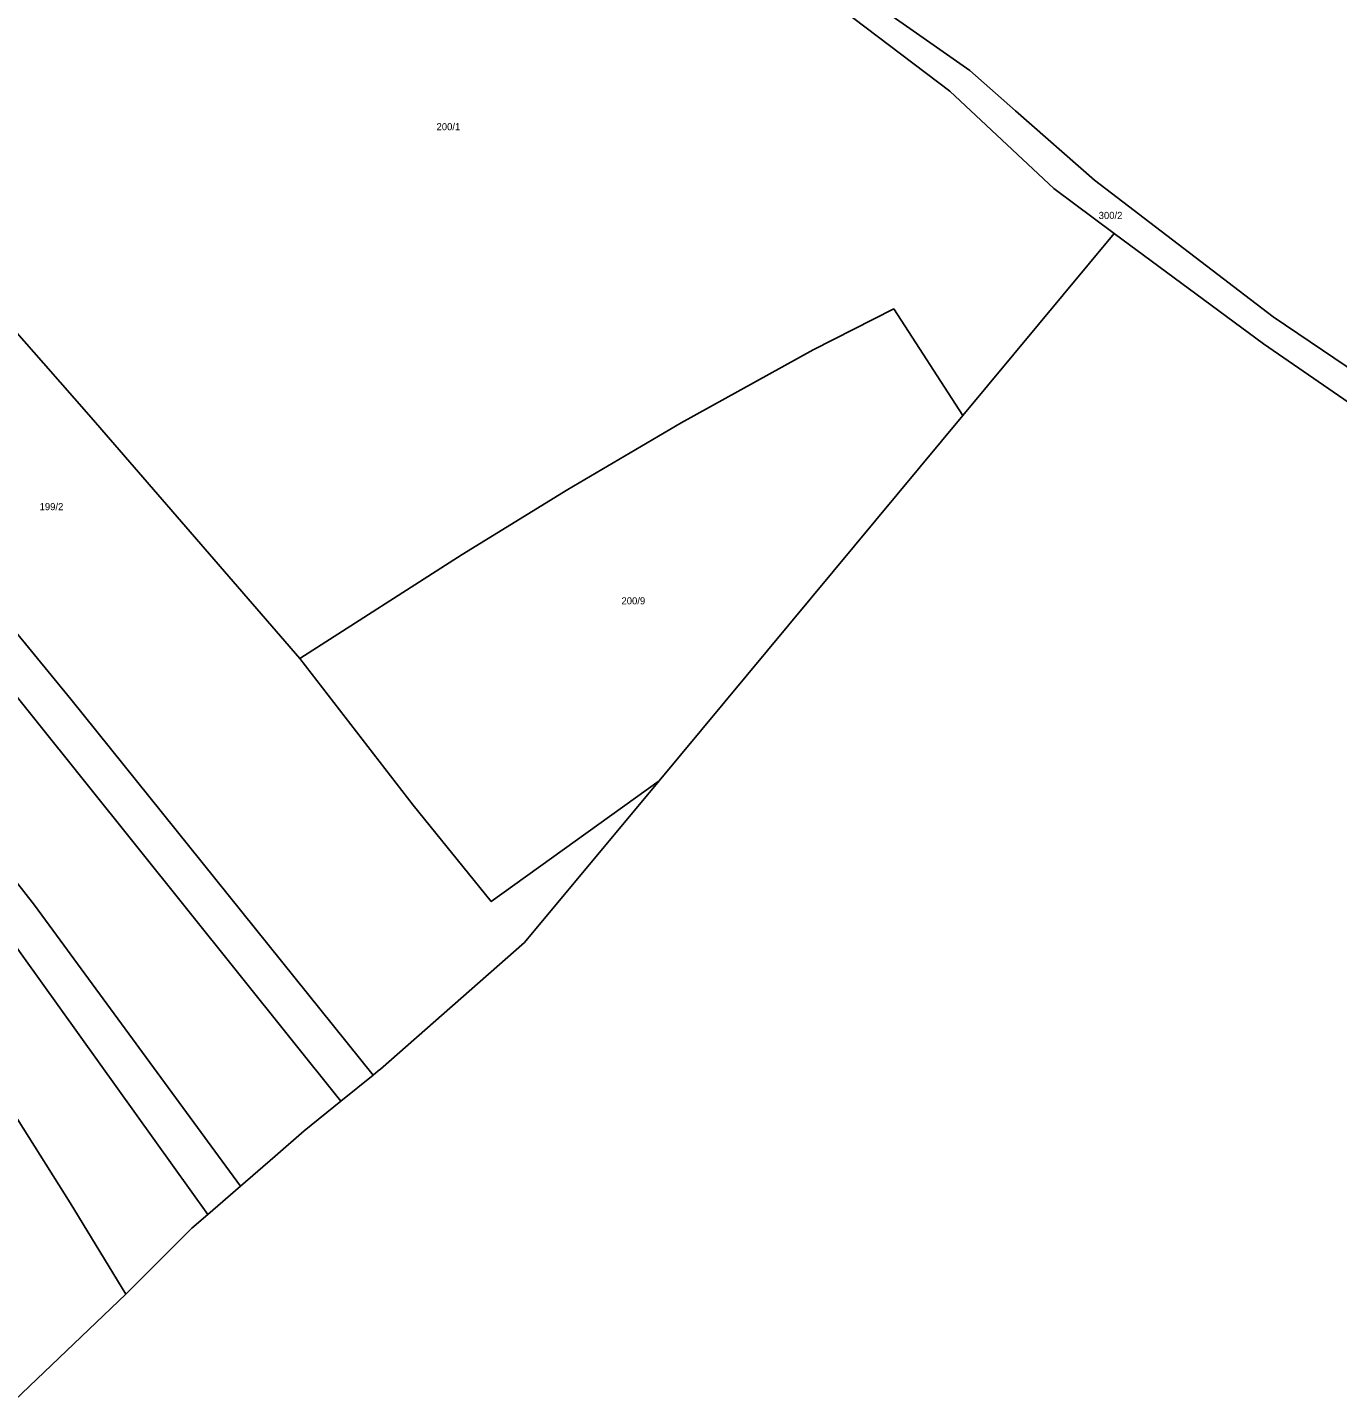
# Model space of a CAD drawing. Extents: x -779723 to -777378, y -1011169 to -1009297.
# Drawn here: x -778975.2 to -778661.4, y -1011038.3 to -1010709.6 of the extents above; entities that cross this region are included whole.
import ezdxf

# ---------------------------------------------------------------- set-up
doc = ezdxf.new("R2010")
doc.units = 0
doc.layers.add('Hranice parcel', color=7, linetype='Continuous')
doc.layers.add('Parcelní čísla', color=7, linetype='Continuous')

msp = doc.modelspace()

# ---------------------------------------------------------------- linework, layer by layer
at = {"layer": 'Hranice parcel'}
for p, q in [((-778751.14, -1010802.45), (-778714.89, -1010758.88)), ((-778714.89, -1010758.88), (-778679.13, -1010785.37)), ((-778679.13, -1010785.37), (-778631.26, -1010818.25)), ((-778823.91, -1010889.93), (-778751.14, -1010802.45)), ((-778856.16, -1010928.69), (-778823.91, -1010889.93)), ((-778890.63, -1010958.98), (-778856.16, -1010928.69)), ((-778900.11, -1010966.64), (-778892.41, -1010960.42)), ((-778932.03, -1010993.77), (-778924.2, -1010986.99)), ((-778978.29, -1011038.33), (-778951.63, -1011012.88))]:
    msp.add_line(p, q, dxfattribs=at)
for points in [[(-778905.58, -1010527.64), (-778886.77, -1010581.17), (-778868.96, -1010613.49), (-778842.93, -1010647.4), (-778817.25, -1010670.8), (-778782.47, -1010696.78), (-778749.49, -1010719.92), (-778738.54, -1010729.52), (-778719.6, -1010746.13), (-778676.79, -1010778.85), (-778624.16, -1010814.46), (-778586.31, -1010838.48), (-778546.61, -1010880.74), (-778543.66, -1010884.4)], [(-778714.89, -1010758.88), (-778729.33, -1010748.14), (-778754.23, -1010724.83), (-778783.19, -1010702.88)], [(-779090.15, -1010715.21), (-779038.14, -1010781.12), (-778964.83, -1010870.44), (-778892.41, -1010960.42)], [(-779034.27, -1010715.3), (-779007.39, -1010749.08), (-778971.37, -1010789.97), (-778959.93, -1010803), (-778909.95, -1010860.69)], [(-779096.96, -1010721.21), (-778998.61, -1010843.93), (-778900.11, -1010966.64)], [(-779114.85, -1010739.08), (-779044.24, -1010829.34), (-778973.49, -1010919.73), (-778924.2, -1010986.99)], [(-778932.03, -1010993.77), (-778944.73, -1010976.05), (-778980.97, -1010925.46), (-778998.02, -1010902.45), (-779043.05, -1010846.46), (-779121, -1010745.73)], [(-778951.63, -1011012.88), (-778964.98, -1010991), (-778997.44, -1010939.52), (-779063.39, -1010851.12), (-779129.44, -1010762.47)], [(-778909.95, -1010860.69), (-778871.06, -1010835.79), (-778845.77, -1010820.21), (-778818.59, -1010804.27), (-778786.97, -1010786.76), (-778767.72, -1010776.97), (-778751.14, -1010802.45)], [(-778823.91, -1010889.93), (-778864.11, -1010918.86), (-778882.79, -1010895.75), (-778909.95, -1010860.69)], [(-778892.41, -1010960.42), (-778891.19, -1010959.43), (-778890.63, -1010958.98)], [(-778924.2, -1010986.99), (-778915.9, -1010979.8), (-778908.89, -1010973.74), (-778900.11, -1010966.64)], [(-778951.63, -1011012.88), (-778935.84, -1010997.06), (-778932.03, -1010993.77)]]:
    msp.add_lwpolyline(points, dxfattribs=at)

# ---------------------------------------------------------------- texts
at = {"layer": 'Parcelní čísla'}
for s, p in [('200/1', (-778877.22, -1010734.19)), ('300/2', (-778718.62, -1010755.43)), ('199/2', (-778972.29, -1010825.16)), ('200/9', (-778832.92, -1010847.71))]:
    msp.add_text(s, height=1.7, dxfattribs=at).set_placement(p)

doc.saveas('drawing.dxf')
